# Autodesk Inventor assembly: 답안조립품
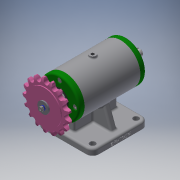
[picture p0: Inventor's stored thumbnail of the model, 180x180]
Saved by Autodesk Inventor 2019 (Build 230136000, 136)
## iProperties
Created: 2019-06
Part Number: 답안조립품
Material: 일반
Document SubType Name: Assembly
Designer: SCD-A08
Author: SCD-A08
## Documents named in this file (11)
- C:\Users\SCD-A08\Desktop\490604V1029\답안조립품.iam
- C:\Users\SCD-A08\Desktop\490604V1029\본체.ipt
- C:\Users\SCD-A08\Desktop\490604V1029\베어링 6203.ipt
- C:\Users\SCD-A08\Desktop\490604V1029\볼트 M4.ipt
- C:\Users\SCD-A08\Desktop\490604V1029\스프로킷.ipt
- C:\Users\SCD-A08\Desktop\490604V1029\스프링와셔.ipt
- C:\Users\SCD-A08\Desktop\490604V1029\오일 실 17 30 5.ipt
- C:\Users\SCD-A08\Desktop\490604V1029\축.ipt
- C:\Users\SCD-A08\Desktop\490604V1029\커버.ipt
- C:\Users\SCD-A08\Desktop\490604V1029\키 4x4x12.ipt
- C:\Users\SCD-A08\Desktop\490604V1029\평와셔.ipt
